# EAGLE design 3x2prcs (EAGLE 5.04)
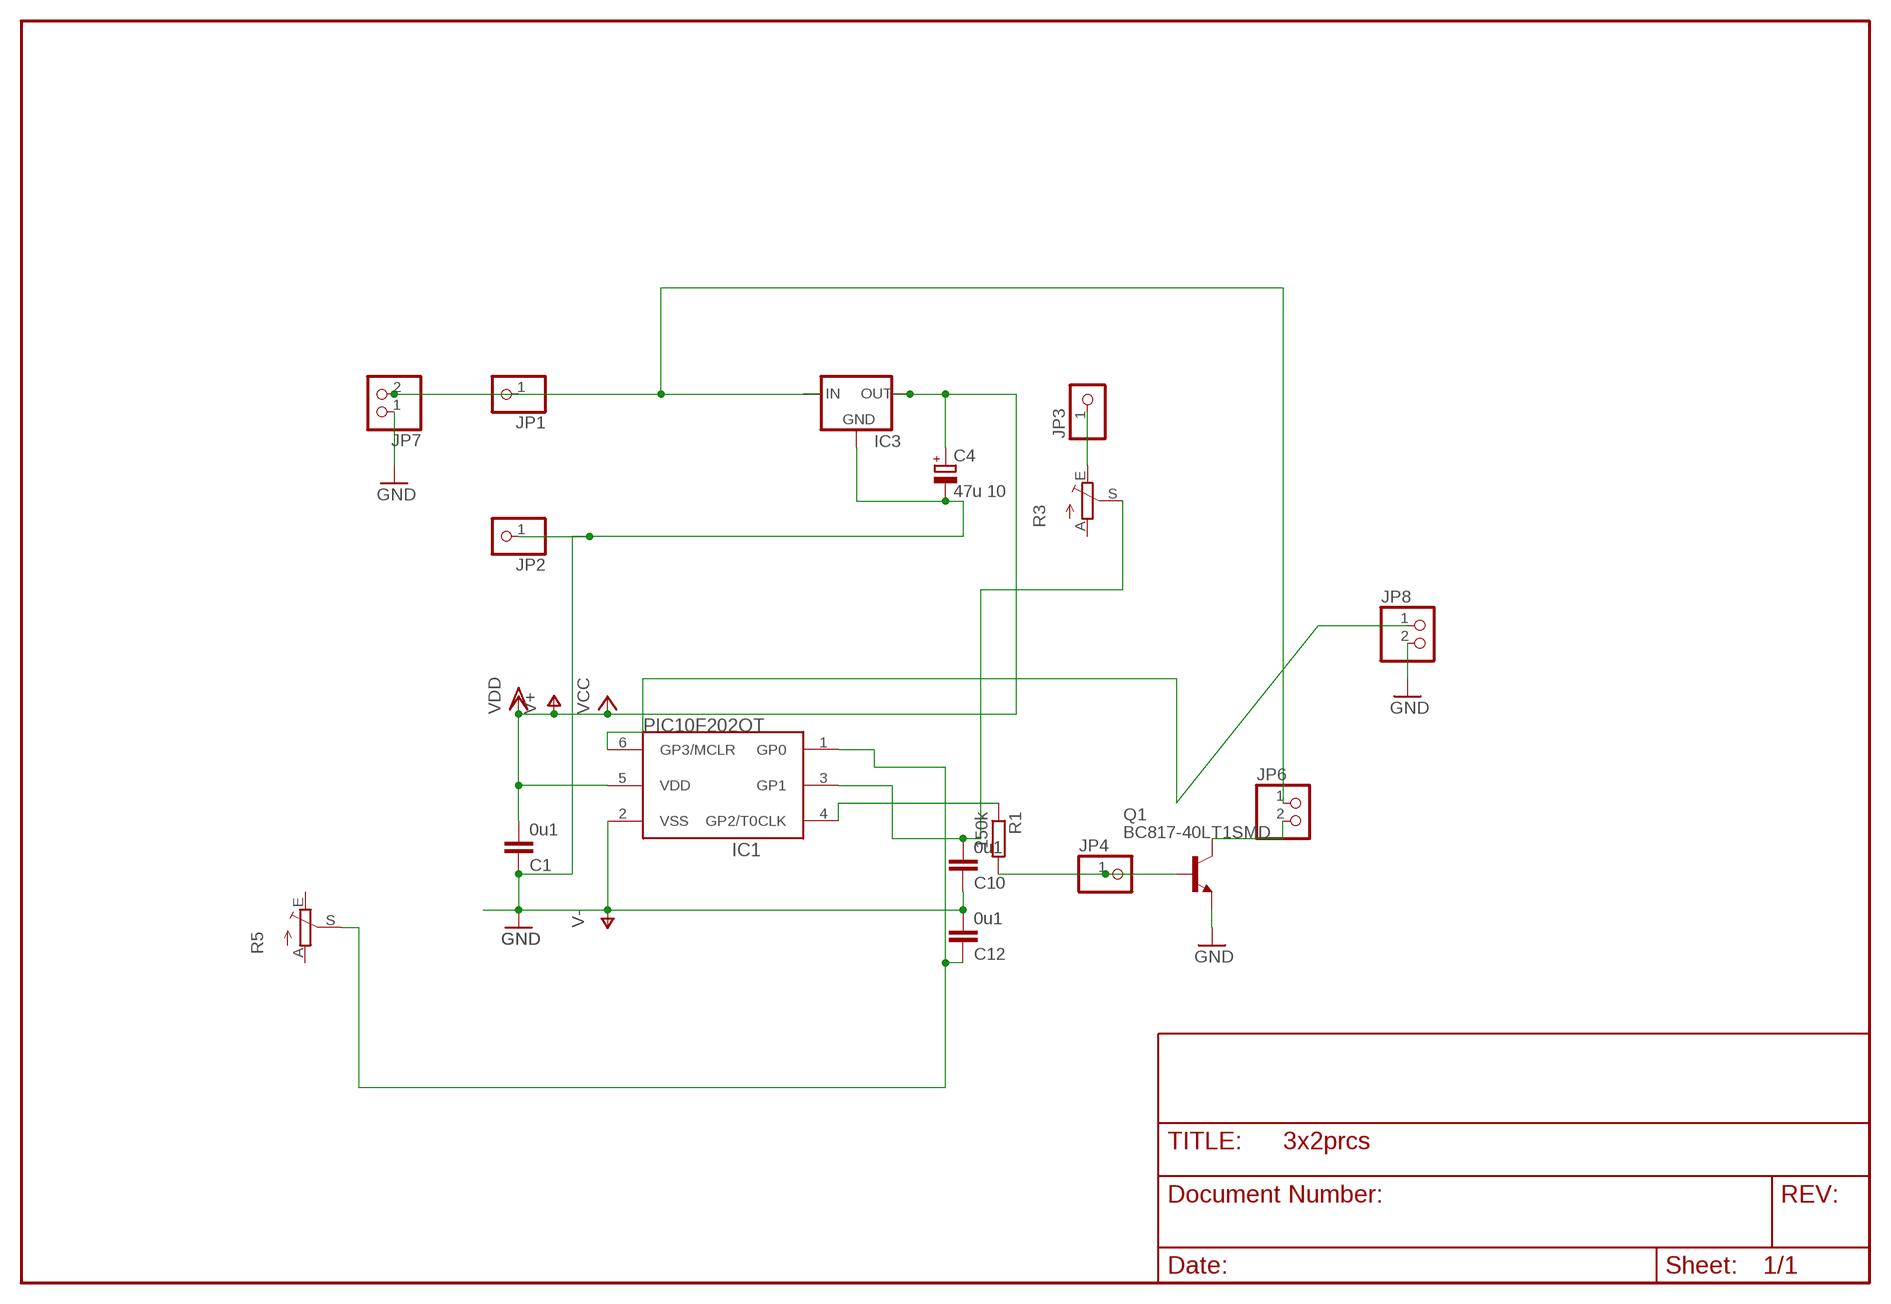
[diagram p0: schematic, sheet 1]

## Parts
C1  0u1  C-EUC1206  [C1206]
C4  47u 10  CPOL-EUE2.5-6  [E2,5-6]
C10  0u1  C-EUC0805  [C0805]
C12  0u1  C-EUC0805  [C0805]
IC1  PIC10F202OT  [SOT23-6]
IC3  78LXX  [78LXX]
JP1  PINHD-1X1  [1X01]
JP2  PINHD-1X1  [1X01]
JP3  PINHD-1X1  [1X01]
JP4  PINHD-1X1  [1X01]
JP6  PINHD-1X2  [1X02]
JP7  PINHD-1X2  [1X02]
JP8  PINHD-1X2  [1X02]
Q1  BC817-40LT1SMD  [SOT23-BEC]
R1  150k  R-EU_R0805  [R0805]
R3  TRIM_EU-CA6V  [CA6V]
R5  TRIM_EU-CA6V  [CA6V]

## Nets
GND: C1.1 C4.- C10.1 C12.2 IC1.2(VSS) IC3.GND JP2.1 JP7.1 JP8.2 Q1.E ; supply symbol labelled V-
N$1: JP3.1 R3.E
N$2: JP4.1 Q1.B R1.2
N$3: IC1.6(GP3/MCLR) JP8.1
N$4: JP6.2 Q1.C
N$5: IC1.4(GP2/T0CLK) R1.1
N$12: C10.2 IC1.3(GP1) R3.S
N$13: C12.1 IC1.1(GP0) R5.S
N$20: IC3.IN JP1.1 JP6.1 JP7.2
V+: C1.2 C4.+ IC1.5(VDD) IC3.OUT ; supply symbol labelled VCC, VDD
Unconnected: R3.A R5.A R5.E

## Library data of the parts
C1 C10 C12 = rcl:C-EU: CAPACITOR, European symbol
C4 = rcl:CPOL-EU: POLARIZED CAPACITOR, European symbol
IC1 = microchip-5:PIC10F20*: uPC nW 0,25/0,5k Program Flash memory
IC3 = v-reg:78LXX: VOLTAGE REGULATOR
JP1-JP4 = pinhead:PINHD-1X1: PIN HEADER
JP6-JP8 = pinhead:PINHD-1X2: PIN HEADER
Q1 = transistor-npn:BC817*: NPN Transistor
R1 = rcl:R-EU_: RESISTOR, European symbol
R3 R5 = pot:TRIM_EU-: POTENTIOMETER

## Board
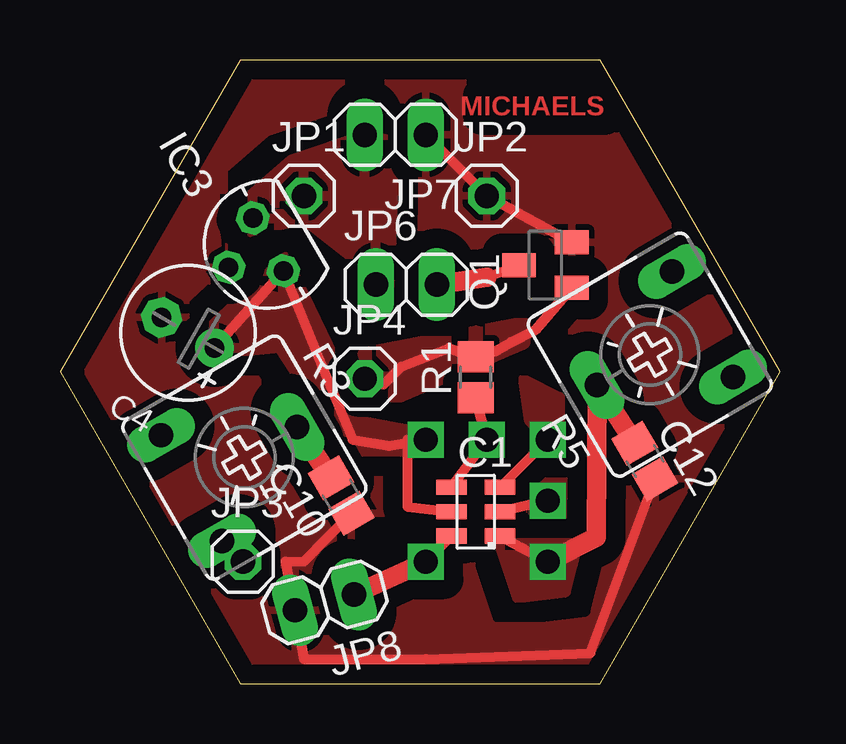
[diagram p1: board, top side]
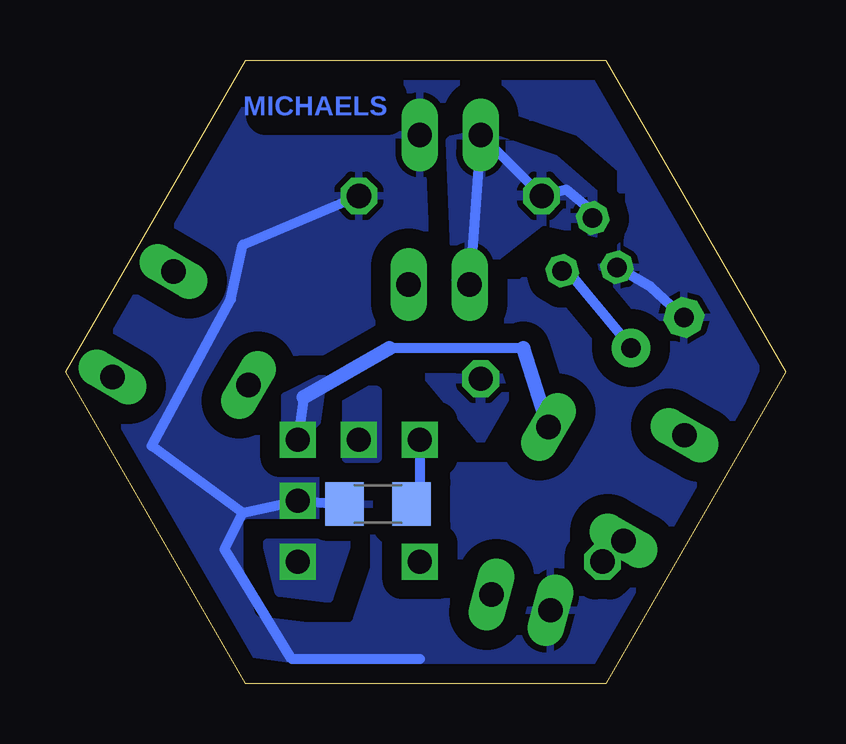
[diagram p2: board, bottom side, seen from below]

Size 30 x 25.98 mm. Coordinates in mm from the lower left corner, seen from the top.
Outline: 7.5,0 22.5,0 30,12.99 22.5,25.98 7.5,25.98 0,12.99 7.5,0
Copper layers (1*16): Top 0.035mm / dielectric 1.5mm / Bottom 0.035mm
Design rules "default *": minimum track width 10mil, minimum drill 24mil, track to track 8mil, track to pad 8mil, pad to pad 8mil, via to via 8mil, smd to smd 8mil, copper to edge 10mil, drill to drill 8mil, minimum pad ring 10mil, minimum via ring 8mil, stop-mask expansion 4mil, vias tented up to drill 0mil, thermal gap 10mil

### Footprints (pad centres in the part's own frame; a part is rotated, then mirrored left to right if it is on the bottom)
C1206 = smd 1.6 x 1.8: 1 -1.4,0; 2 1.4,0
E2,5-6 = drill 0.813 pad 1.6 round: + -1.27,0 | drill 0.813 pad 1.6 octagon: - 1.27,0
C0805 = smd 1.3 x 1.5: 1 -0.85,0; 2 0.85,0
SOT23-6 = smd 0.635 x 1.27: 1 -1.016,-1.016; 2 0,-1.016; 3 1.016,-1.016; 4 1.016,1.016; 5 0,1.016; 6 -1.016,1.016
78LXX = drill 0.813 octagon: GND 0,1.905; IN 1.27,0; OUT -1.27,0
1X01 = drill 1.016 octagon: 1 0,0
1X02 = drill 1.016 long: 1 -1.27,0; 2 1.27,0
SOT23-BEC = smd 1 x 1.4: B -0.95,-1.1; C 0,1.1; E 0.95,-1.1
R0805 = smd 1.3 x 1.5: 1 -0.85,0; 2 0.85,0
CA6V = drill 1.016 long: A -2.54,-2.54; E 2.54,-2.54; S 0,2.54

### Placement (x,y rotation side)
C1  16.98,7.48 0 bottom
C4  5.33,14.62 150 top
C10  11.72,7.83 120 top
C12  24.37,9.27 300 top
IC1  17.32,7.16 90 top
IC3  8.67,18.3 120 top
JP1  10.16,20.32 0 top
JP2  17.78,20.32 0 top
JP3  7.62,5.08 0 top
JP4  12.7,12.7 0 top
JP6  14.43,16.62 0 top
JP7  13.97,22.86 180 top
JP8  11.03,3.38 195 top
Q1  20.22,17.44 90 top
R1  17.32,12.76 90 top
R3  7.68,9.41 300 top
R5  24.58,13.7 120 top

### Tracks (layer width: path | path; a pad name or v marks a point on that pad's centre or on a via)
GND  (via drill 1)
  Top 0.406: v20.32,7.62 IC1.2 | Q1.E JP2.1 JP7.1 | C12.2 22.1,1.27 15.24,1.02 10.16,1.02 JP8.2 9.4,5.09 10.16,5.08 C10.1
  Bottom 0.406: C1.1 v20.32,7.62 22.61,7.11 | 15.24,1.02 20.57,1.02 23.37,5.59 22.61,7.11 | 22.61,7.11 26.42,9.91 23.11,16 22.61,18.29 JP2.1 | IC3.GND 5.59,16.51 C4.-
  pour Top (isolate 0.813, rank 4): 30.05,13 23.09,0 7.34,0 0.62,13.77 6.9,25.08 22.48,25.85
  pour Bottom (isolate 0.813, rank 4): 24.25,22.54 29.85,12.7 23.09,1.35 7.34,-0.79 0.82,13.97 6.96,25.01 22.34,25.73
N$1
  Top 0.406: R3.E JP3.1
N$2
  Top 0.406: JP4.1 13.48,12.46 14.22,13.21 16.2,13.97 R1.2 18.18,13.87 18.8,14.22 19.82,14.73 Q1.B
  pour Bottom (isolate 0.813): 12.7,10.16 11.68,11.94 11.94,13.21 15.24,13.21
  pour Top (isolate 0.61): 13.21,12.45 12.7,13.72 19.3,14.99 19.3,14.22 13.97,11.94
N$3  (via drill 1)
  Top 0.406: v15.24,5.08 IC1.6
  Top 0.813: JP8.1 v15.24,5.08
N$4
  Top 0.406: 17.78,16.93 Q1.C
  Top 0.813: JP6.2 17.78,16.93
N$5  (via drill 1)
  Top 0.406: IC1.4 v17.78,10.16 R1.1
  pour Bottom (isolate 0.61): 18.29,9.4 17.02,9.4 17.02,12.19 18.29,12.19
N$7
  Bottom 0.406: 6.6,14.22 9.14,17.27
N$12  (via drill 1)
  Top 0.406: v20.32,10.16 IC1.3
  Top 0.813: C10.2 R3.S
  Bottom 0.406: 10.92,13.97 16.51,13.97 | 20.07,11.94 v20.32,10.16
  Bottom 0.61: R3.S 10.92,13.97 | 16.51,13.97 20.07,11.94
  pour Top: 20.32,10.16 19.56,10.92 19.3,12.7 20.83,11.94 20.83,10.41
  pour Bottom: 20.32,10.16 19.56,10.92 19.3,12.7 20.83,11.94 20.83,10.41
N$13  (via drill 1)
  Top 0.406: IC1.1 v20.32,5.08
  Top 0.813: v20.32,5.08 22.35,6.1 R5.S C12.1
  pour Bottom (isolate 0.61): 18.29,5.84 19.05,3.56 21.08,3.81 21.59,5.84
  pour Top (isolate 0.61): 18.29,5.84 19.05,3.56 21.08,3.81 21.59,5.84
N$20
  Bottom 0.406: JP6.1 JP7.2 JP1.1 9.14,20.57 7.62,19.3 IC3.IN
  pour Top (isolate 0.813): 12.7,22.86 13.97,22.61 13.72,16.51 10.16,19.3 7.87,18.8 7.62,20.07 9.65,21.84
  pour Bottom: 12.7,22.86 13.97,22.61 13.72,16.51 10.16,19.3 7.87,18.8 7.62,20.07 9.65,21.84
V+  (via drill 1)
  Top 0.406: IC1.5 14.48,7.37 14.48,8.64 14.48,10.16 v15.24,10.16 13.72,9.91 12.19,10.16 10.92,13.21 IC3.OUT C4.+
  Bottom 0.406: C1.2 15.24,7.62 v15.24,10.16
  pour Top (isolate 0.813): 5.84,14.48 9.4,17.78 12.7,10.92 15.49,10.41 15.49,9.65 11.94,9.65 9.14,13.97 6.6,13.72

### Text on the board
Top: MICHAELS
Bottom: MICHAELS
